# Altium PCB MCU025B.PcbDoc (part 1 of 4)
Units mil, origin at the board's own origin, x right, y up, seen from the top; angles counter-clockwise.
Board outline 2300 x 6150 mil, 6 copper layers (Top Signal, GND, Middle Signal, PWR, GND2, Bottom Signal), stack 61.64 mil thick; 237 components, 197 nets, 910 pads, 404 vias.
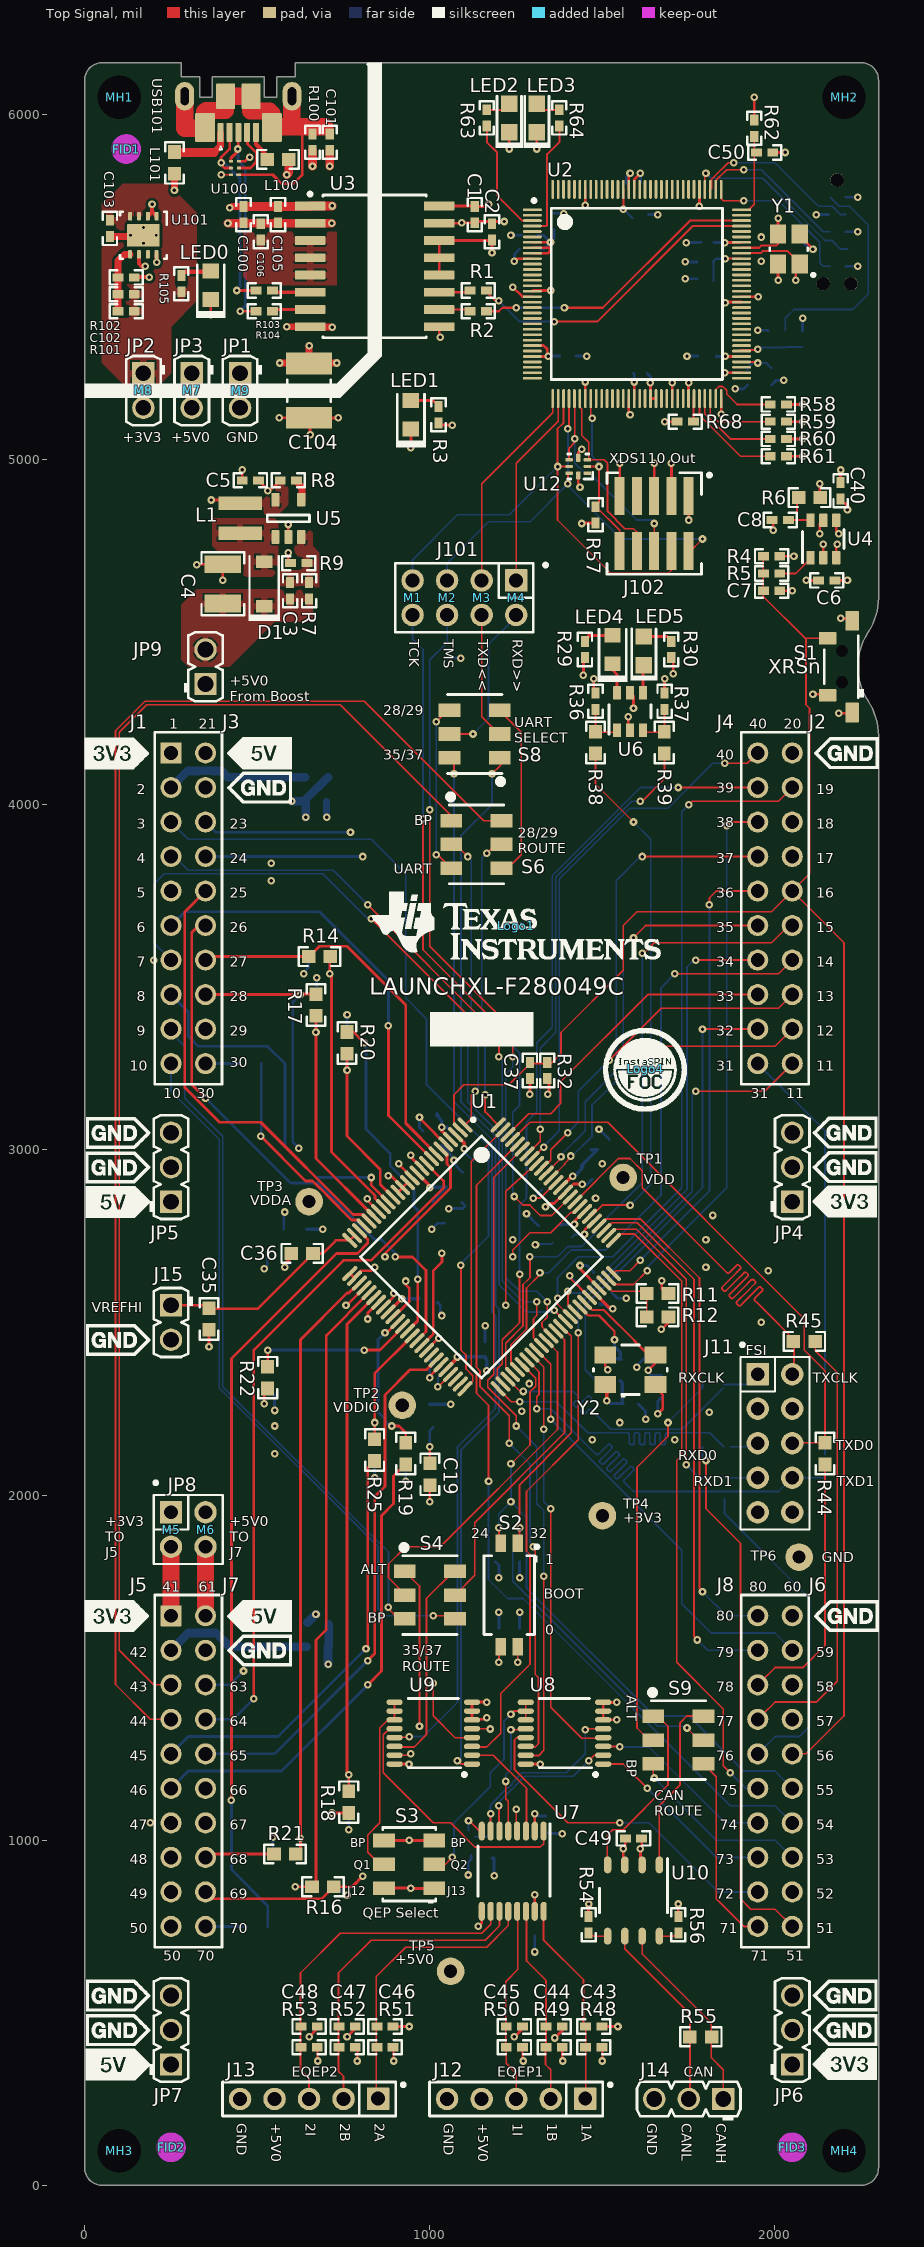
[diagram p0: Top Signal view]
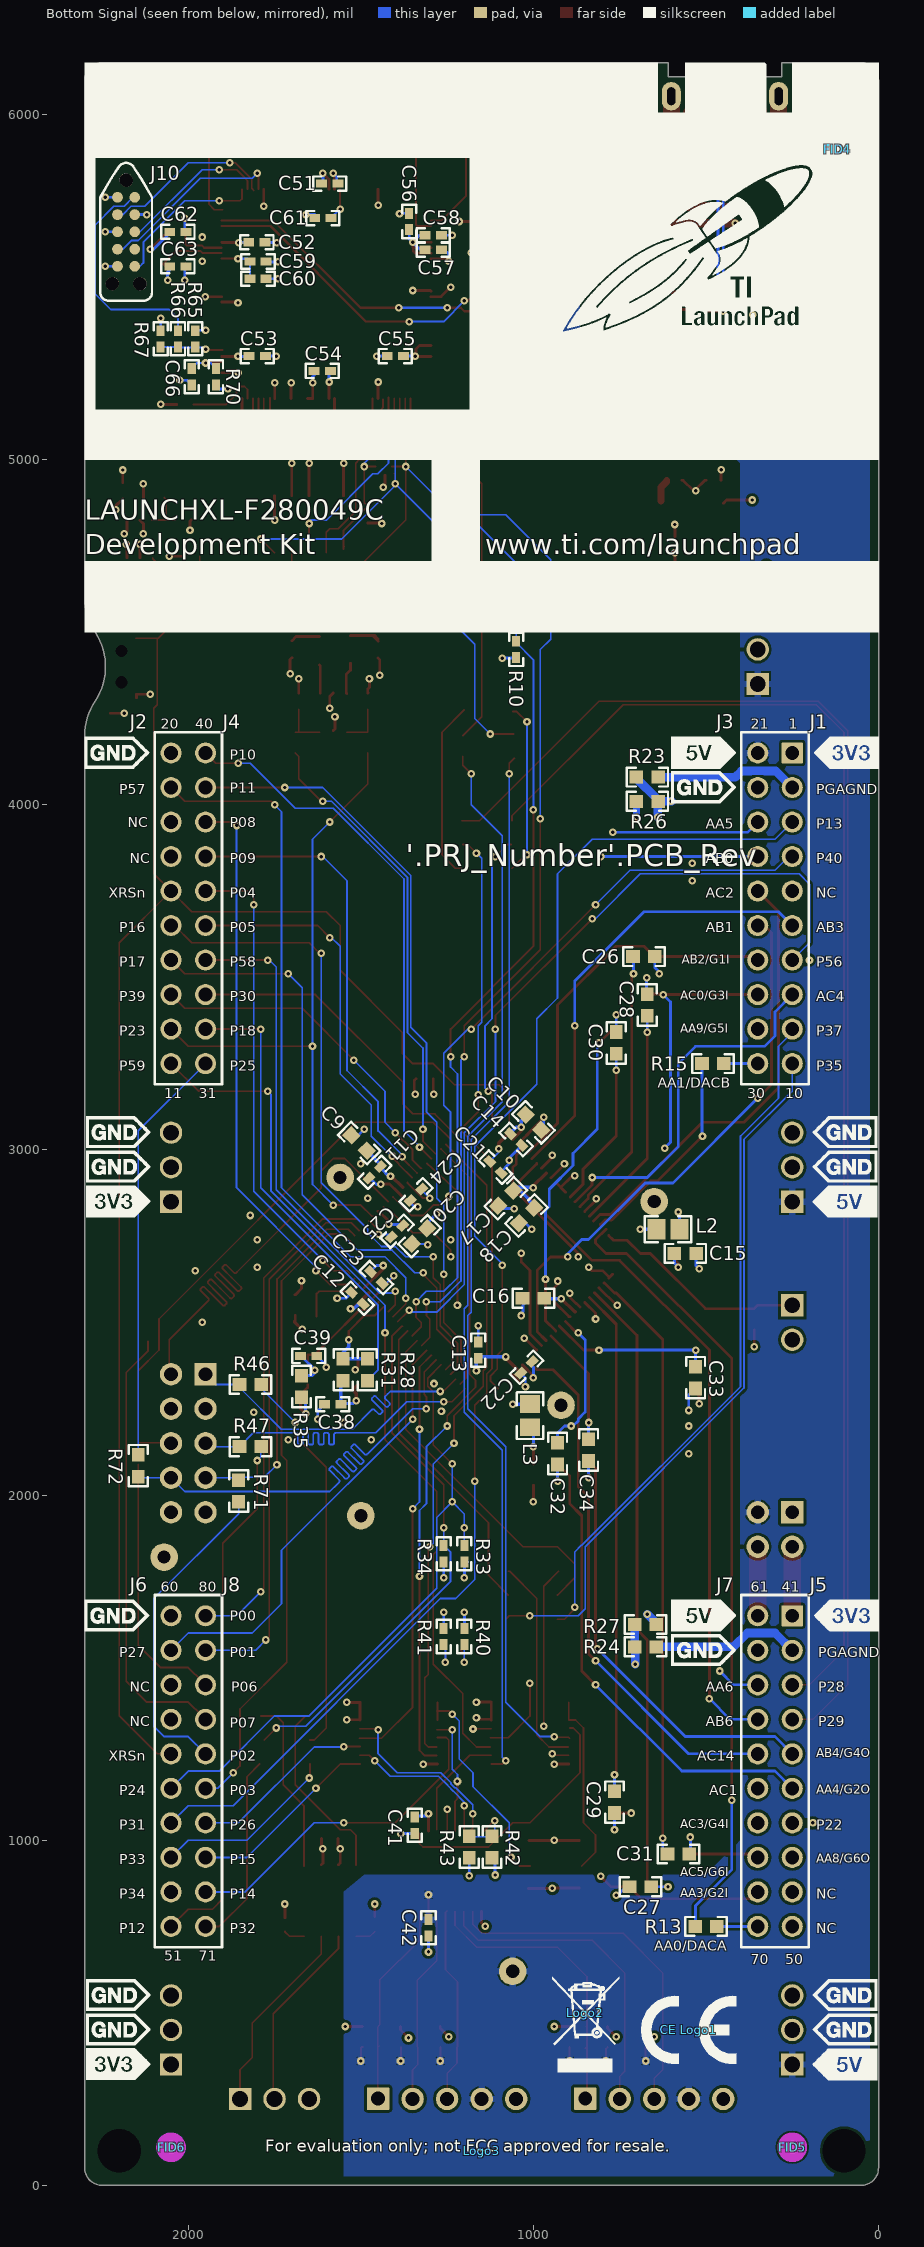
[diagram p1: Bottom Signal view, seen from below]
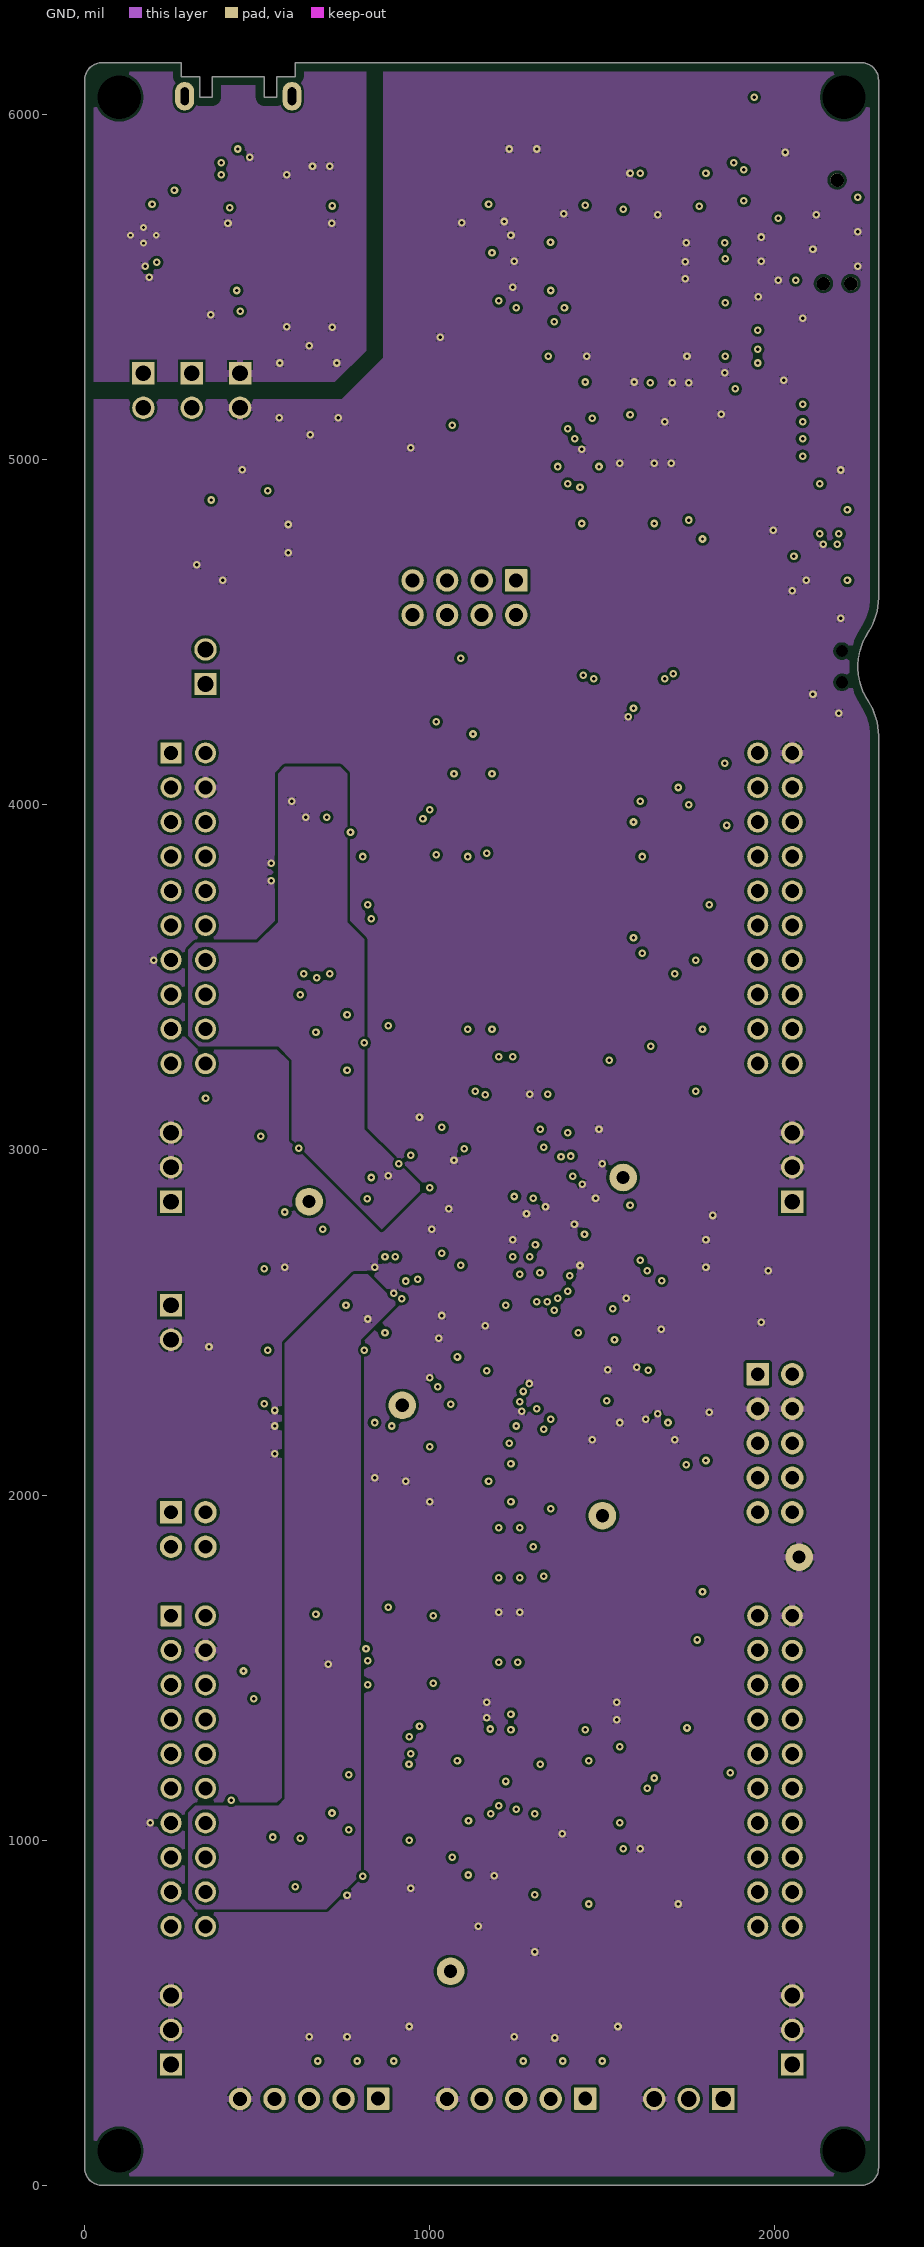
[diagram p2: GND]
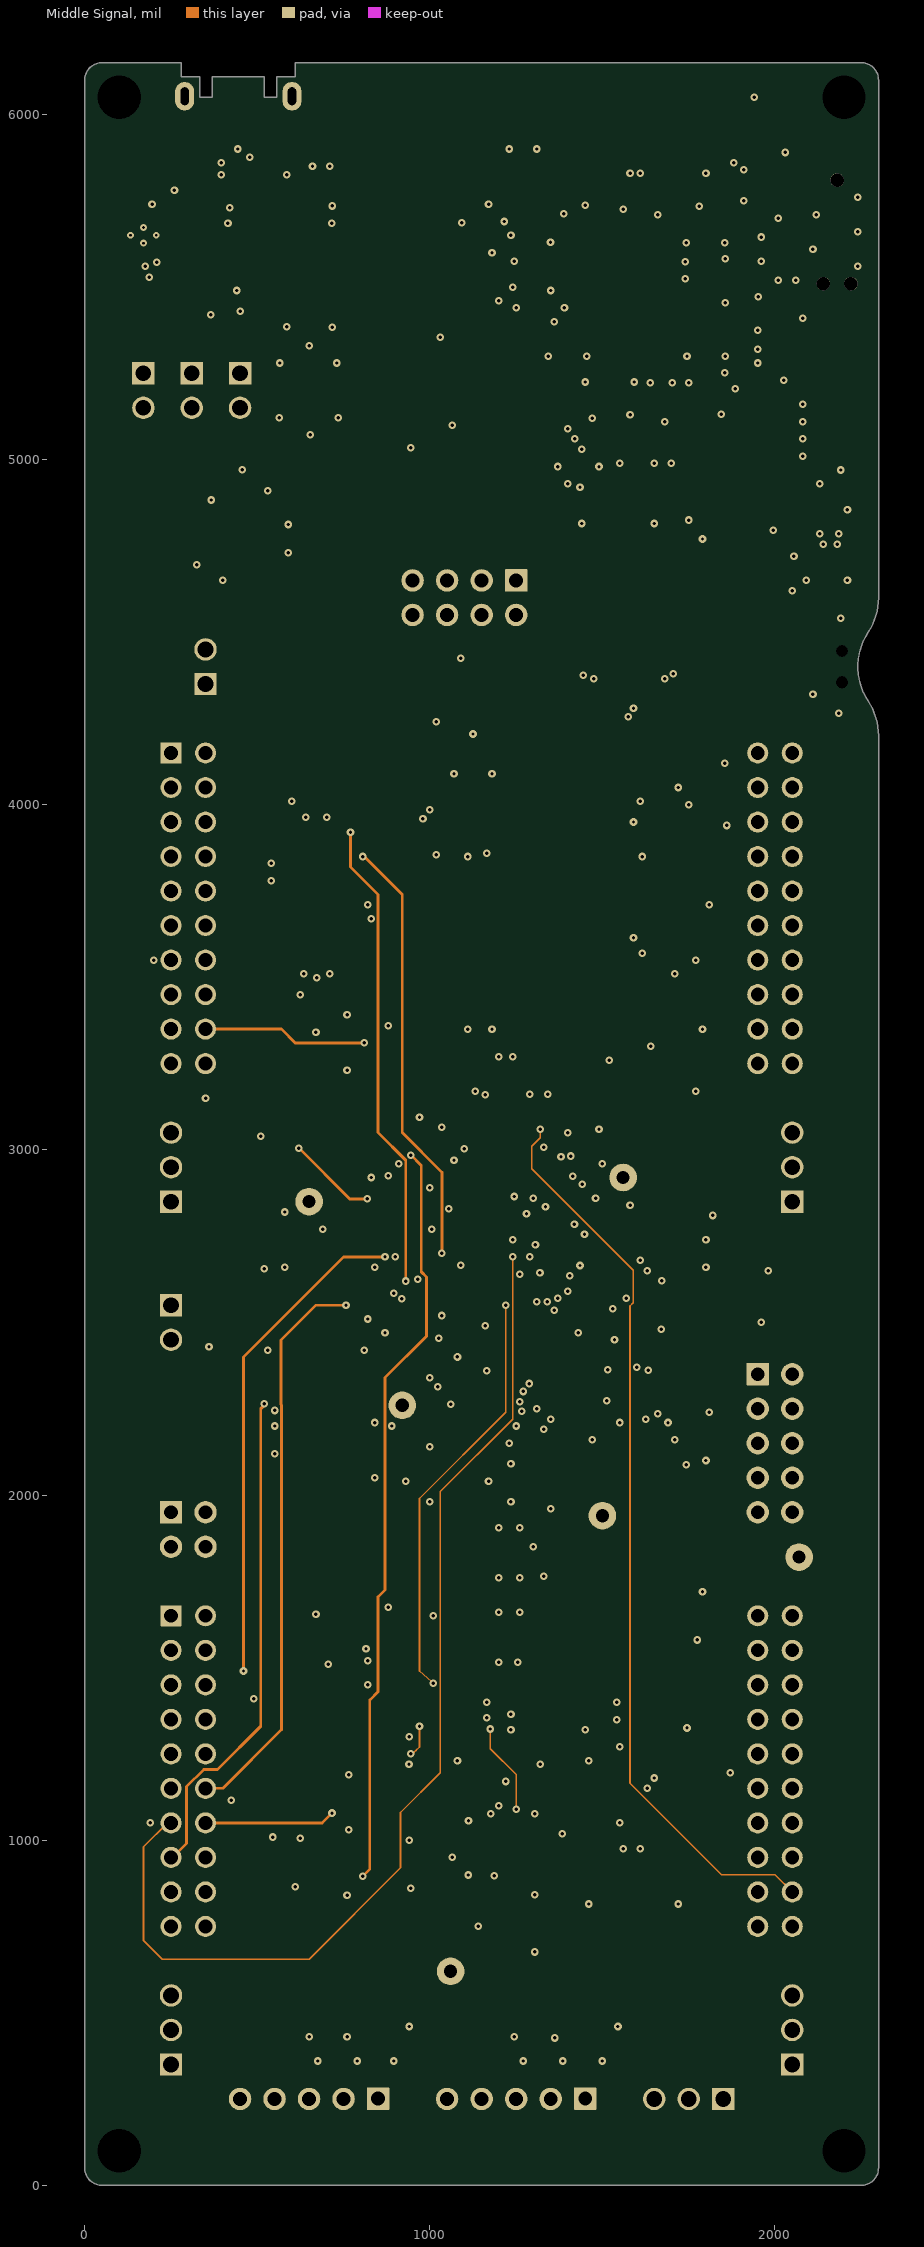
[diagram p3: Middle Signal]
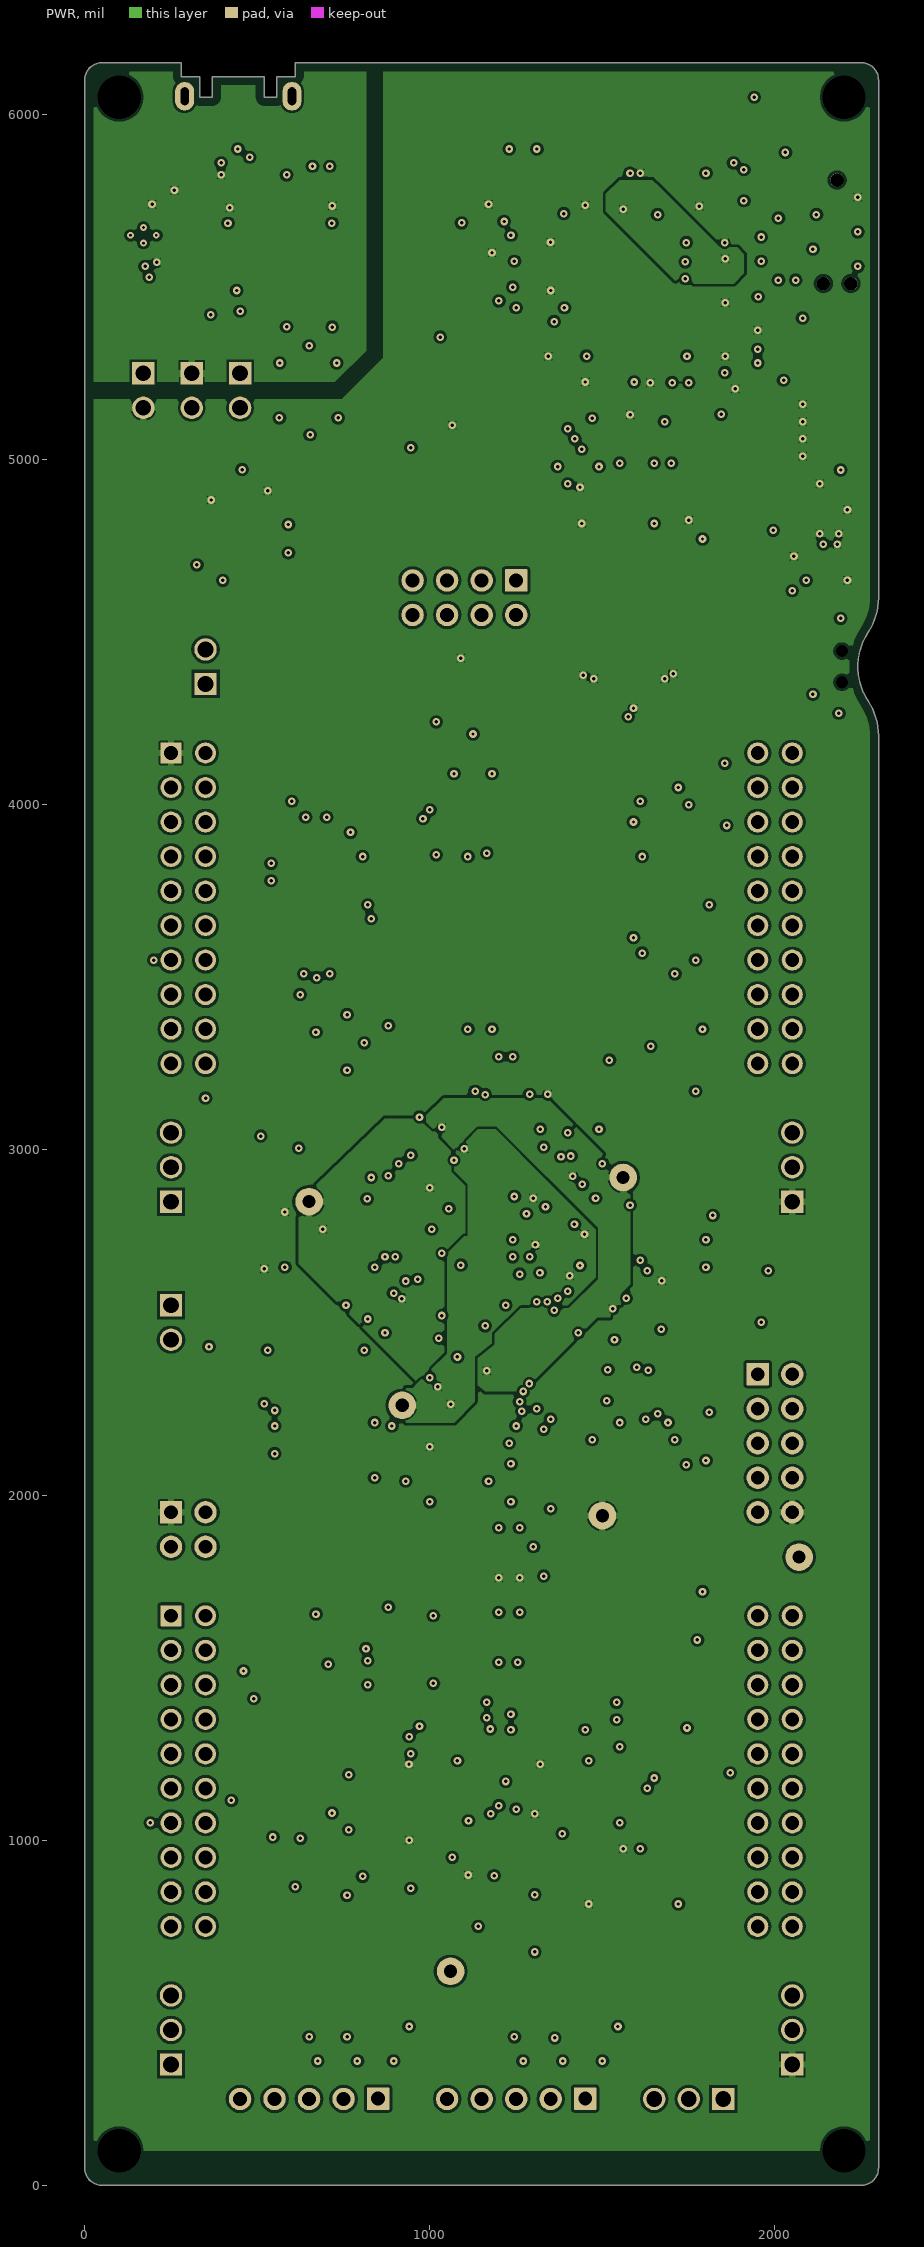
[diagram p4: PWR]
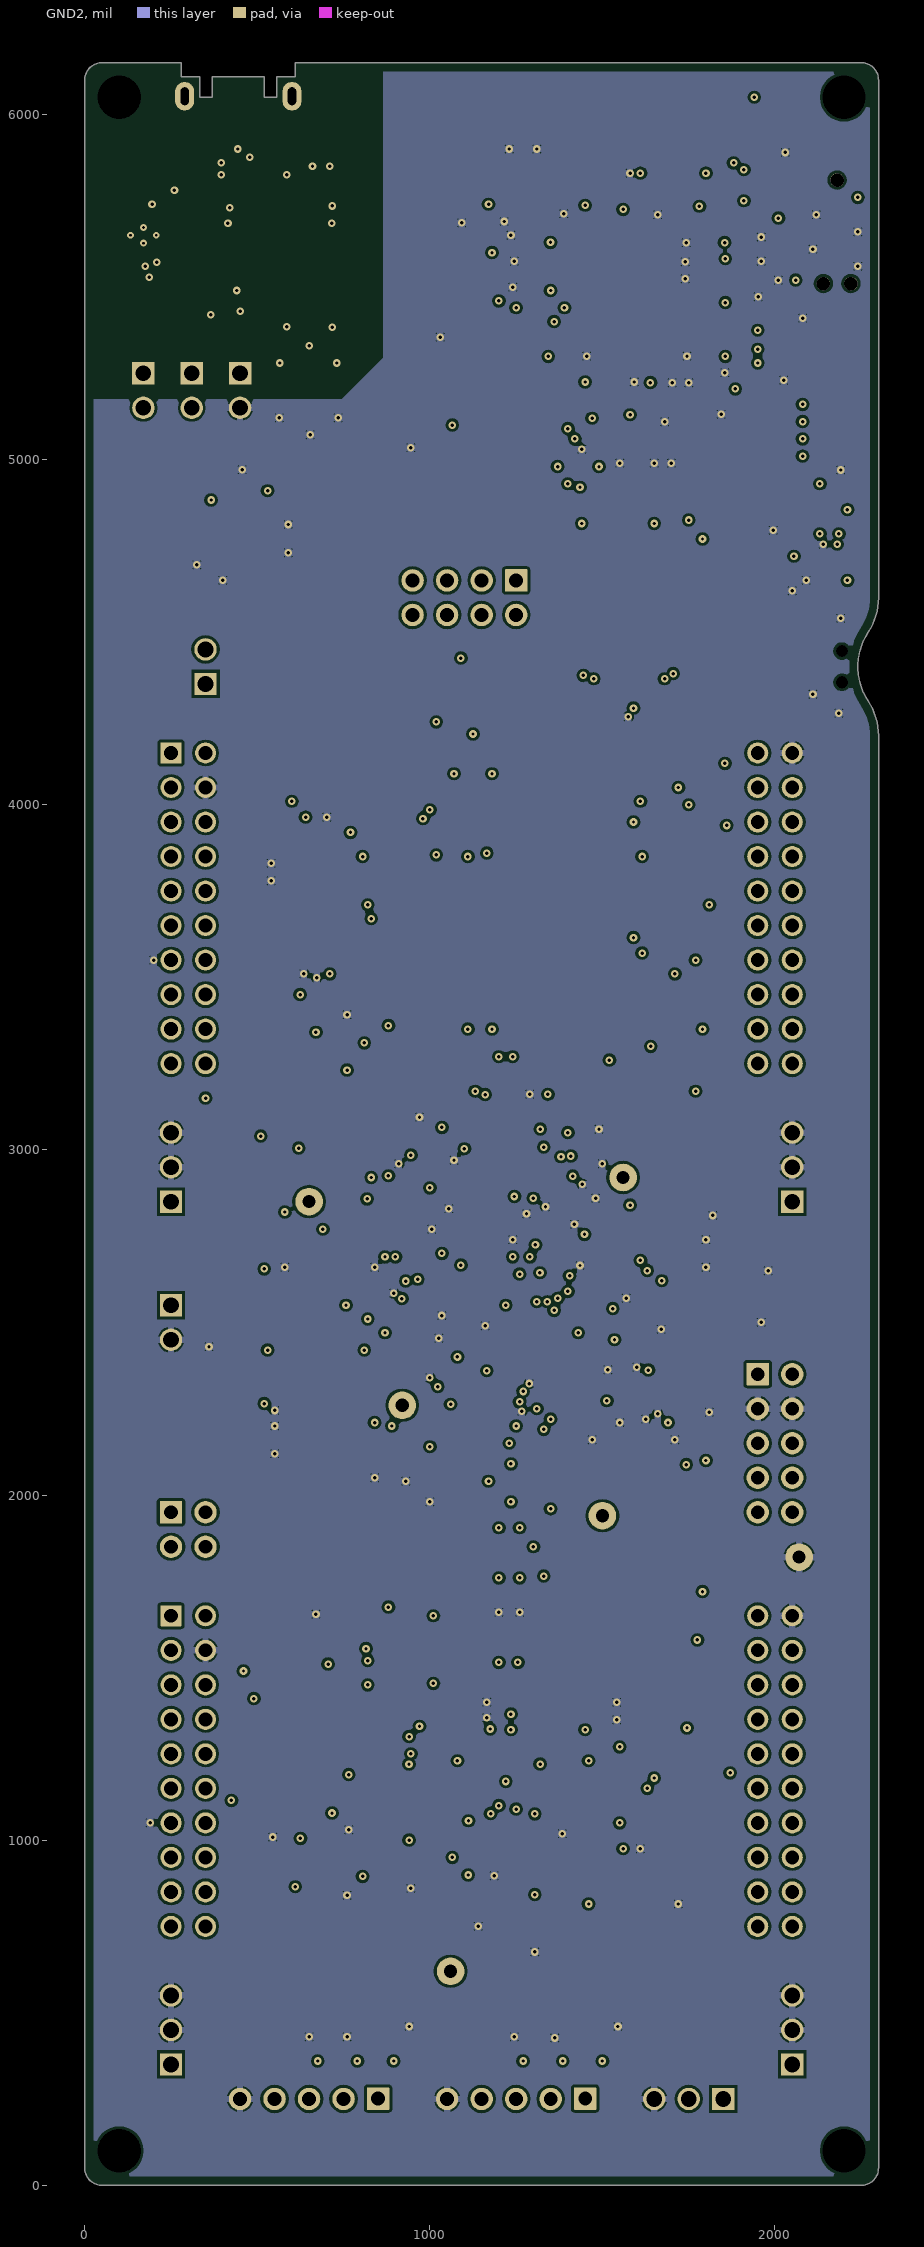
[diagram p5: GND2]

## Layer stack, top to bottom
Top Solder: solder mask 0.4, Solder Resist, Dk 3.5
Top Signal: signal copper 1.4
Dielectric 1: prepreg 6.25, FR-4, Dk 4.2
GND: signal copper 1.4
Dielectric 2: core 16.1, FR-4, Dk 4.2
Middle Signal: signal copper 1.4
Dielectric 3: prepreg 8.54, FR-4, Dk 4.2
PWR: signal copper 1.4
Dielectric 4: core 16.1, FR-4, Dk 4.2
GND2: signal copper 1.4
Dielectric 5: prepreg 6.25, FR-4, Dk 4.2
Bottom Signal: signal copper 1.4
Bottom Solder: solder mask 0.4, Solder Resist, Dk 3.5

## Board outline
50,0 cw(c50,50) 0,50 0,6100 cw(c50,6100) 50,6150 280,6150 280,6110 333,6110 333,6050 370,6050 370,6110 520,6110 520,6050 557,6050 557,6110 610,6110 610,6150 2250,6150 cw(c2250,6100) 2300,6100 2300,4600 cw(c2118.33,4600) 2270,4500 ccw(c2421.67,4400) 2270,4300 cw(c2118.33,4200) 2300,4200 2300,50 cw(c2250,50) 2250,0

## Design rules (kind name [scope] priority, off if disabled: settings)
AcuteAngle [All] p1: minimum=4.50000000000000E+0001 checktracksonly=TRUE
AssemblyTestPointUsage [All] p1: valid=2
BoardOutlineClearance BoardOutlineClearance_MountingHoles [OnCopper and InComponentClass('Mounting Holes')] p1: gap=40 ignorepadtopadclearanceinfootprint=FALSE
BoardOutlineClearance BoardOutlineClearance_Poly [OnCopper and IsPoly] p2: gap=25 ignorepadtopadclearanceinfootprint=FALSE
BoardOutlineClearance [OnCopper and Not InComponentClass('Logo') and not InComponentClass('FiducialMark') and not InRegion(1000,500,4000,800) and not InPoly] p3: gap=10 ignorepadtopadclearanceinfootprint=FALSE
Clearance Clearance_Boardedge [OnCopper and Not InComponentClass('Logo') and not InComponentClass('FiducialMark') and not IsKeepOut vs IsKeepOut] p1: gap=5 ignorepadtopadclearanceinfootprint=FALSE
Clearance Clearance_FiducialMark [InComponentClass('FiducialMark') vs InComponentClass('FiducialMark')] p2: gap=0 ignorepadtopadclearanceinfootprint=TRUE
Clearance Clearance_Keepouts [((IsTrack Or IsArc) And Not InPoly) And IsFree and IsKeepOut vs ((IsTrack Or IsArc) And Not InPoly) And IsFree and IsKeepOut] p3: gap=5 ignorepadtopadclearanceinfootprint=FALSE
Clearance Clearance_Poly [InPolygon] p4: gap=8 ignorepadtopadclearanceinfootprint=FALSE
Clearance [All] p5: gap=5 ignorepadtopadclearanceinfootprint=FALSE
ComponentClearance "ComponentClearance_overlay to overlay" [OnBottomSilkscreen vs OnTopSilkscreen] p1: gap=0 collisioncheckmode=3 verticalgap=0 showdistances=FALSE
ComponentClearance ComponentClearance_MountingHoles_FiducialMarks [InComponentClass('Mounting Holes') vs InComponentClass('FiducialMark')] p2: gap=50 collisioncheckmode=3 verticalgap=10 showdistances=FALSE
ComponentClearance ComponentClearance_Shunt [InComponentClass('Header') vs InComponentClass('Shunt')] p3: gap=0 collisioncheckmode=3 verticalgap=0 showdistances=FALSE
ComponentClearance ComponentClearance_Logo [InComponentClass('Logo')] p4: gap=0 collisioncheckmode=3 verticalgap=0 showdistances=FALSE
ComponentClearance ComponentClearance_Logo_1 [InComponentClass('Logo') vs InComponentClass('Logo')] p5: gap=0 collisioncheckmode=3 verticalgap=0 showdistances=FALSE
ComponentClearance ComponentClearance_ScrewToNut [(HasFootprint('NY PMS 440 0025 PH')) vs (HasFootprint('Keystone_1902C'))] p6: gap=5 collisioncheckmode=3 verticalgap=10 showdistances=FALSE
ComponentClearance ComponentClearance_MountingHoles [InComponentClass('Mounting Holes')] p7: gap=250 collisioncheckmode=3 verticalgap=100000 showdistances=FALSE
ComponentClearance ComponentClearance_SmallPassives [HasFootprint('0201*') or HasFootprint('0402*') or HasFootprint('0508') or HasFootprint('0603*') or HasFootprint('0612') or HasFootprint('0805*') or HasFootprint('0815*') or HasFootprint('0830*') or HasFootprint('1206*') or HasFootprint('1210*') or HasFootprint('1808*') or HasFootprint('1812*') or HasFootprint('1825*') or HasFootprint('2010*') or HasFootprint('2220*') or HasFootprint('2225*') or HasFootprint('2512*') or HasFootprint('2728*') or HasFootprint('3518*') vs HasFootprint('0201*') or HasFootprint('0402*') or HasFootprint('0508') or HasFootprint('0603*') or HasFootprint('0612') or HasFootprint('0805*') or HasFootprint('0815*') or HasFootprint('0830*') or HasFootprint('1206*') or HasFootprint('1210*') or HasFootprint('1808*') or HasFootprint('1812*') or HasFootprint('1825*') or HasFootprint('2010*') or HasFootprint('2220*') or HasFootprint('2225*') or HasFootprint('2512*') or HasFootprint('2728*') or HasFootprint('3518*')] p8: gap=10 collisioncheckmode=3 verticalgap=0 showdistances=FALSE
ComponentClearance ComponentClearance_THtoSMT [IsThruComponent vs IsSMTComponent] p9: gap=10 collisioncheckmode=3 verticalgap=10 showdistances=FALSE
ComponentClearance ComponentClearance_THtoTH [IsThruComponent vs IsThruComponent] p10: gap=20 collisioncheckmode=3 verticalgap=30 showdistances=FALSE
DiffPairsRouting [All] p1: maxlimit=100 minlimit=10 mostfreqgap=10 toplayer_minwidth=15 toplayer_maxwidth=15 toplayer_prefwidth=15 midlayer1_minwidth=15 midlayer1_maxwidth=15 midlayer1_prefwidth=15 midlayer2_minwidth=15 midlayer2_maxwidth=15 midlayer2_prefwidth=15 midlayer3_minwidth=15 midlayer3_maxwidth=15 midlayer3_prefwidth=15 midlayer4_minwidth=15 midlayer4_maxwidth=15 midlayer4_prefwidth=15 bottomlayer_minwidth=15 bottomlayer_maxwidth=15 bottomlayer_prefwidth=15 maxuncoupledlength=1000
FabricationTestPointUsage TestPointUsage [All] p1: valid=2 allowmultiple=FALSE
FabricationTestpoint Testpoint [All] p1: side=3 testpointundercomponent=TRUE minsize=40 maxsize=100 preferedsize=60 minholesize=0 maxholesize=40 preferedholesize=32 testpointgrid=1 allowsidetop=TRUE allowsidebottom=TRUE usegrid=TRUE gridtolerance=0.01
FanoutControl Fanout_LCC [IsLCC] p1: bgadir=Out bgaviamode=Centered fanoutstyle=Auto fanoutdirection=Alternating viagrid=1 // Fanout_LCC (Default Rule)
FanoutControl Fanout_BGA [IsBGA] p2: bgadir=Out bgaviamode=Centered fanoutstyle=Auto fanoutdirection=Alternating viagrid=1 // Fanout_BGA (Default Rule)
FanoutControl Fanout_Default [All] p4: bgadir=Out bgaviamode=Centered fanoutstyle=Auto fanoutdirection=Alternating viagrid=1 // Fanout_Default (Default Rule)
FanoutControl Fanout_Small [(CompPinCount < 5)] p5: bgadir=Out bgaviamode=Centered fanoutstyle=Auto fanoutdirection=OutThenIn viagrid=1 // Fanout_Small (Default Rule)
HoleSize [All] p1: absolutevalues=TRUE maxlimit=251 minlimit=10 maxpercent=80.000 minpercent=20.000
MatchedLengths FSIRX [InNetClass('FSIRX')] p1: tolerance=25 checknetsindiffpair=FALSE checkdiffpairvsdiffpair=TRUE checkxsignals=TRUE checkothers=TRUE
MatchedLengths FSITX [InNetClass('FSITX')] p2: tolerance=25 checknetsindiffpair=FALSE checkdiffpairvsdiffpair=TRUE checkxsignals=TRUE checkothers=TRUE
MinimumAnnularRing MinimumAnnularRing_ThermalPadVias [IsVia and InAnyComponent] p1: minimumring=5
MinimumAnnularRing [All] p2: minimumring=6
MinimumSolderMaskSliver MinimumSolderMaskSliver_Logo [InComponentClass('Logo') vs InComponentClass('Logo')] p1: minsoldermaskwidth=0.7
MinimumSolderMaskSliver [All] p2: minsoldermaskwidth=3
PlaneClearance [All] p1: clearance=5
PlaneConnect [All] p1: planeconnectstyle=Relief reliefexpansion=10 reliefentries=4 reliefconductorwidth=25 reliefairgap=10
PolygonConnect [All] p1: connectstyle=Relief reliefconductorwidth=20 reliefentries=4 polygonreliefangle="90 Angle" airgapwidth=5
RoutingVias ThermalPadVias [IsVia and InAnyComponent] p1: holewidth=7.87 width=19.68 viastyle="Through Hole" minholewidth=7.87 minwidth=19.68 maxholewidth=12.99 maxwidth=23.62
RoutingVias [All] p2: holewidth=10 width=22 viastyle="Through Hole" minholewidth=10 minwidth=22 maxholewidth=40 maxwidth=65
SilkToBoardRegionClearance [Not ((IsComment or IsDesignator) And (Hide <> 'False')) and not InRegion(1000,500,4000,800)] p1:
SilkToSilkClearance SilkToSilkClearance_Pb-FreeLogo [(HasFootprint('Pb-Free_Overlay_Medium') OR HasFootprint('Pb-Free_Overlay_Small')) vs (HasFootprint('Pb-Free_Overlay_Medium') OR HasFootprint('Pb-Free_Overlay_Small'))] p1: silktosilkclearance=0
SilkToSilkClearance [All] p2: silktosilkclearance=3
SilkToSolderMaskClearance SilkToComponentPadClearance [(IsPad or IsFill or IsRegion) and InAnycomponent] p1: minsilkscreentomaskgap=3 clearancetoexposedcopper=TRUE
SilkToSolderMaskClearance "Silk to Solder Mask Opening" [All] p2: minsilkscreentomaskgap=3 clearancetoexposedcopper=TRUE
SolderMaskExpansion [All] p1: expansion=2
Width Analog [InNetClass('Analog')] p1: maxlimit=25 minlimit=8 preferedwidth=8
Width [All] p2: maxlimit=100 minlimit=5 preferedwidth=5 checkconnectedcopper=TRUE
14 further rules are at their usual default settings.

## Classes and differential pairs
net class Analog: ADCINA0 ADCINA1 ADCINA2 ADCINA3_P2I ADCINA4_P2OF ADCINA5 ADCINA6 ADCINA8_P6OF ADCINA9_P5I ADCINB0 ADCINB1 ADCINB2_P1I ADCINB3 ADCINB4_P4OF ADCINC0_P3I ADCINC1 ADCINC2 ADCINC3_P4I ADCINC4 ADCINC5_P6I ADCINC14 GND NetC26_2 NetC27_2 NetC28_2 NetC29_2 NetC30_2 NetC31_2 NetC32_1 NetC33_1 NetC34_1 NetC35_1 NetR13_2 NetR15_2 NetR23_1 NetR24_1 PGA135_GND PGA246_GND
component class MCU025B_XDS110_USB_Power: C1 C2 C3 C4 C5 C6 C7 C8 C100 C101 C102 C103 C104 C105 C106 D1 JP1 JP2 JP3 JP4 JP5 JP6 JP7 JP9 JP10 L1 L100 L101 LED0 LED1 R1 R2 R3 R4 R5 R6 R7 R8 R9 R100 R101 R102 R103 R104 R105 TP1 TP2 TP3 TP4 TP5 TP6 U3 U4 U5 U100 U101 USB101
component class MCU025B_XDS110_Target_Interface: J101 J102 R57 U12
component class MCU025B_XDS110_MCU: C50 C51 C52 C53 C54 C55 C56 C57 C58 C59 C60 C61 C62 C63 C66 J10 LED2 LED3 R58 R59 R60 R61 R62 R63 R64 R65 R66 R67 R68 R70 R? U2 Y1
component class MCU025B_F280049C_Device: C9 C10 C11 C12 C13 C14 C15 C16 C17 C18 C19 C20 C21 C22 C23 C24 C25 C26 C27 C28 C29 C30 C31 C32 C33 C34 C35 C36 C67 J15 L2 L3 R10 R11 R12 R13 R14 R15 R16 R17 R18 R19 R20 R21 R22 R23 R24 R25 R26 R27 U1
component class MCU025B_Connectors: C43 C44 C45 C46 C47 C48 C49 J1 J2 J5 J6 J11 J12 J13 J14 JP8 R48 R49 R50 R51 R52 R53 R54 R55 R56 U10
component class MCU025B_AltRouting_Misc: C37 C38 C39 C40 C41 C42 LED4 LED5 R28 R29 R30 R31 R32 R33 R34 R35 R36 R37 R38 R39 R40 R41 R42 R43 R44 R45 R46 R47 R71 R72 S1 S2 S3 S4 S6 S8 S9 U6 U7 U8 U9 Y2
component class Header: J11 J12 J13 J14 J15 J101 JP1 JP2 JP3 JP4 JP5 JP6 JP7 JP8 JP9 JP10
component class AssemblyNote: ZZ2 ZZ3 ZZ4
component class FiducialMark: FID1 FID2 FID3 FID4 FID5 FID6
component class MCU025B_Hardware: "CE Logo1" FID1 FID2 FID3 FID4 FID5 FID6 Logo1 Logo2 Logo3 Logo4 M1 M2 M3 M4 M5 M6 M7 M8 M9 MH1 MH2 MH3 MH4 ZZ2 ZZ3 ZZ4
component class Logo: Logo1 Logo4
net class FSIRX: GPIO2_FSIRXD1 GPIO12_FSIRXD0 GPIO33_FSIRXCLK
net class FSITX: GPIO6_FSITXD0 GPIO7_FSITXCLK GPIO25_FSITXD1
component class Shunt: M1 M2 M3 M4 M5 M6 M7 M8 M9

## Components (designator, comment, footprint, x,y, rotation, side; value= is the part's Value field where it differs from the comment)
C1 "GRM155R71A104KA01D" 0402 1130,5710 r90 top value=0.1uF
C2 "GRM155R71A104KA01D" 0402 1180,5660 r270 top value=0.1uF
C3 "GRM1555C1H821JA01D" 0402 595,4620 r90 top value=820pF
C4 "GRM32DR71E106KA12L" 1210_220 400,4640 r90 top value=10uF
C5 "GRM155R60J475ME47D" 0402 480,4940 r180 top value=4.7uF
C6 "GRM155R71A104KA01D" 0402 2150,4650 r0 top value=0.1uF
C7 "GRM155R71E103KA01D" 0402 1990,4620 r0 top value=0.01uF
C8 "GRM155R71E103KA01D" 0402 2015,4825 r180 top value=0.01uF
C9 "GRM188R61A106ME69D" 0603 1505,3020 r225 bottom value=10uF
C10 "GRM188R61A106ME69D" 0603 1000,3080 r45 bottom value=10uF
C11 "GRM155R71A104KA01D" 0402 1460,2935 r315 bottom value=0.1uF
C12 "GRM155R71A104KA01D" 0402 1510,2570 r45 bottom value=0.1uF
C13 "GRM155R71A104KA01D" 0402 1160,2420 r90 bottom value=0.1uF
C14 "GRM155R71A104KA01D" 0402 1050,3030 r225 bottom value=0.1uF
C15 "GRM188R61A225KE34D" 0603 560,2700 r0 bottom value=2.2uF
C16 "GRM188R61A225KE34D" 0603 1000,2570 r0 bottom value=2.2uF
C17 "GRM188R61A225KE34D" 0603 1080,2860 r315 bottom value=2.2uF
C18 "GRM188R61A225KE34D" 0603 1020,2810 r315 bottom value=2.2uF
C19 "GRM188R61A106ME69D" 0603 1000,2060 r270 top value=10uF
C20 "GRM188R61A106ME69D" 0603 1330,2750 r135 bottom value=10uF
C21 "GRM155R71A104KA01D" 0402 1110,2950 r45 bottom value=0.1uF
C22 "GRM155R71A104KA01D" 0402 1020,2370 r315 bottom value=0.1uF
C23 "GRM155R71A104KA01D" 0402 1455,2630 r225 bottom value=0.1uF
C24 "GRM155R71A104KA01D" 0402 1340,2870 r135 bottom value=0.1uF
C25 "GRM155R71A104KA01D" 0402 1395,2764 r315 bottom value=0.1uF
C26 "GRM1885C1H331JA01D" 0603 680,3560 r0 bottom value=330pF
C27 "GRM1885C1H331JA01D" 0603 690,865 r180 bottom value=330pF
C28 "GRM1885C1H331JA01D" 0603 670,3420 r270 bottom value=330pF
C29 "GRM1885C1H331JA01D" 0603 765,1110 r90 bottom value=330pF
C30 "GRM1885C1H331JA01D" 0603 760,3310 r270 bottom value=330pF
C31 "GRM1885C1H331JA01D" 0603 580,960 r0 bottom value=330pF
C32 "GRM1885C1H331JA01D" 0603 930,2120 r270 bottom value=330pF
C33 "GRM1885C1H331JA01D" 0603 530,2340 r270 bottom value=330pF
C34 "GRM1885C1H331JA01D" 0603 840,2130 r270 bottom value=330pF
C35 "GRM188R61A225KE34D" 0603 360,2510 r270 top value=2.2uF
C36 "GRM188R61A225KE34D" 0603 630,2700 r180 top value=2.2uF
C37 "GRM155R71A104KA01D" 0402 1290,3230 r90 top value=0.1uF
C38 "GRM1555C1H150JA01D" 0402 1581.21,2262.93 r0 bottom value=15pF
C39 "GRM1555C1H150JA01D" 0402 1651.21,2402.93 r180 bottom value=15pF
C40 "GRM155R71A104KA01D" 0402 2190,4910 r270 top value=0.1uF
C41 "GRM155R71A104KA01D" 0402 1344,1043 r270 bottom value=0.1uF
C42 "GRM155R71A104KA01D" 0402 1304,746 r90 bottom value=0.1uF
C43 "GRM155R71H102KA01D" 0402 1475,460 r0 top value=1000pF
C44 "GRM155R71H102KA01D" 0402 1360,460 r0 top value=1000pF
C45 "GRM155R71H102KA01D" 0402 1245,460 r0 top value=1000pF
C46 "GRM155R71H102KA01D" 0402 870,460 r0 top value=1000pF
C47 "GRM155R71H102KA01D" 0402 760,460 r0 top value=1000pF
C48 "GRM155R71H102KA01D" 0402 650,460 r0 top value=1000pF
C49 "GRM155R71A104KA01D" 0402 1590,1005 r180 top value=0.1uF
C50 "GRM155R71E103KA01D" 0402 1970,5890 r0 top value=0.01uF
C51 "GRM155R71E103KA01D" 0402 1590,5800 r180 bottom value=0.01uF
C52 "GRM155R71E103KA01D" 0402 1801,5630 r180 bottom value=0.01uF
C53 "GRM155R71E103KA01D" 0402 1800,5300 r180 bottom value=0.01uF
C54 "GRM155R70J104KA01D" 0402 1612,5257 r180 bottom value=0.1uF
C55 "GRM155R70J104KA01D" 0402 1400,5300 r0 bottom value=0.1uF
C56 "GRM155R61A105KE15D" 0402 1360,5690 r90 bottom value=1uF
C57 "GRM155R61A105KE15D" 0402 1290,5608 r180 bottom value=1uF
C58 "GRM155R71E103KA01D" 0402 1290,5650 r180 bottom value=0.01uF
C59 "GRM155R60J225KE95D" 0402 1798,5574 r180 bottom value=2.2uF
C60 "GRM155R70J104KA01D" 0402 1798,5524 r180 bottom value=0.1uF
C61 "GRM155R61A105KE15D" 0402 1610,5700 r0 bottom value=1uF
C62 "GRM1555C1H120JA01D" 0402 2030,5660 r0 bottom value=12pF
C63 "GRM1555C1H120JA01D" 0402 2030,5560 r180 bottom value=12pF
C66 "GRM155R70J104KA01D" 0402 1990,5240 r270 bottom value=0.1uF
C100 "GRM155R60J225KE95D" 0402 460,5710 r270 top value=2.2uF
C101 "GRM155R71H332KA01D" 0402 710,5920 r270 top value=3300pF
C102 "GRM1555C1H150JA01D" 0402 120,5479 r180 top value=15pF
C103 "GRM155R60J225KE95D" 0402 73,5670 r270 top value=2.2uF
C104 "1812SC103KAT1A" 1812 650,5200 r90 top value=0.01uF
C105 "GRM155R71A104KA01D" 0402 560,5710 r90 top value=0.1uF
C106 "GRM155R71A104KA01D" 0402 510,5660 r270 top value=0.1uF
"CE Logo1" "CE Mark" CE_Mark_5mm 550,450 r180 bottom
D1 "1N5819HW-7-F" SOD-123 520,4640 r90 top value=40V
FID1 "Fiducial" Fiducial10-20 120,5900 r0 top
FID2 "Fiducial" Fiducial10-20 250,110 r0 top
FID3 "Fiducial" Fiducial10-20 2050,110 r0 top
FID4 "Fiducial" Fiducial10-20 120,5900 r180 bottom
FID5 "Fiducial" Fiducial10-20 250,110 r180 bottom
FID6 "Fiducial" Fiducial10-20 2050,110 r180 bottom
J1 "SSQ-110-03-T-D" BoosterPack_40pin_J1J3 300,3700 r180 bottom locked
J2 "SSQ-110-03-T-D" BoosterPack_40pin_J2J4 2000,3700 r180 bottom locked (schematic designator J4)
J5 "SSQ-110-03-T-D" BoosterPack_40pin_J1J3 300,1200 r180 bottom locked
J6 "SSQ-110-03-T-D" BoosterPack_40pin_J2J4 2000,1200 r180 bottom locked (schematic designator J8)
J10 "TC2050-IDC-NL-FP" Tag_TC2050-NL 2180,5660 r180 bottom locked
J11 "TSW-105-07-G-D" TSW-105-07-G-D 2000,2150 r270 top
J12 "TSW-105-07-G-S" TSW-105-07-X-S 1250,250 r180 top locked
J13 "TSW-105-07-G-S" TSW-105-07-X-S 650,250 r180 top locked
J14 "61300311121" WURTH_61300311121 1750,250 r180 top locked
J15 "61300211121" WURTH_61300211121 250,2500 r270 top locked
J101 "TSW-104-07-G-D" TSW-104-07-G-D 1100,4600 r180 top
J102 "FTSH-105-01-F-DV-K" Samtec_FTSH-105-01-x-DV-K 1650,4815 r270 top
JP1 "61300211121" WURTH_61300211121 450,5200 r270 top
JP2 "61300211121" WURTH_61300211121 170,5200 r270 top
JP3 "61300211121" WURTH_61300211121 310,5200 r270 top
JP4 "61300311121" WURTH_61300311121 2050,2950 r90 top locked
JP5 "61300311121" WURTH_61300311121 250,2950 r90 top locked
JP6 "61300311121" WURTH_61300311121 2050,450 r90 top
JP7 "61300311121" WURTH_61300311121 250,450 r90 top locked
JP8 "TSW-102-07-G-D" TSW-102-07-G-D 300,1900 r270 top
JP9 "61300211121" WURTH_61300211121 350,4400 r90 top
L1 "744025003" WE-TPC_2828 450,4830 r270 top value=3.3uH
L2 "BKP2125HS600-T" 0805 610,2770 r0 bottom value="60 ohm"
L3 "BLM21PG221SN1D" 0805 1010,2230 r90 bottom value="220 ohm"
L100 "742792620" 0603 560,5870 r0 top value="100 ohm"
L101 "742792620" 0603 260,5860 r270 top value="100 ohm"
LED0 "150080SS75000" WL-SMCW_RED_0805 365,5505 r90 top value=Red
LED1 "150080SS75000" WL-SMCW_RED_0805 945,5130 r90 top value=Red
LED2 "LTST-C170TBKT" LTST-C170TBKT_Blue 1230,5990 r270 top value=Blue
LED3 "LTST-C170TBKT" LTST-C170TBKT_Blue 1310,5990 r270 top value=Blue
LED4 "150080SS75000" WL-SMCW_RED_0805 1529.37,4449.84 r90 top value=Red
LED5 "LTST-C171GKT" LED_LTST-C171 1620,4446 r270 top value=Green
Logo1 "Texas Instruments" TI_Stacked_Overlay_Small 1250,3650 r0 top
Logo2 "WEEE logo" WEEE_Minimum 850,500 r180 bottom
Logo3 "FCC disclaimer" FCC_disclaimer 1150,100 r180 bottom
Logo4 "INSTASPIN_FOC_LOGO" INSTASPIN_FOC_LOGO 1625,3235 r0 top
M1 "60900213421" Wurth_60900213421 950,4600 r270 top
M2 "60900213421" Wurth_60900213421 1050,4600 r90 top
M3 "60900213421" Wurth_60900213421 1150,4600 r90 top
M4 "60900213421" Wurth_60900213421 1250,4600 r90 top
M5 "60900213421" Wurth_60900213421 250,1900 r90 top
M6 "60900213421" Wurth_60900213421 350,1900 r90 top
M7 "60900213421" Wurth_60900213421 310,5201 r90 top
M8 "60900213421" Wurth_60900213421 170,5201 r90 top
M9 "60900213421" Wurth_60900213421 450,5200 r90 top
MH1 "MTG_NoPads" NPTH125mil 100,6050 r0 top
MH2 "MTG_NoPads" NPTH125mil 2200,6050 r0 top
MH3 "MTG_NoPads" NPTH125mil 100,100 r0 top
MH4 "MTG_NoPads" NPTH125mil 2200,100 r0 top
R1 "CRCW040224R3FKED" 0402 1140,5490 r0 top value=24.3
R2 "CRCW040224R3FKED" 0402 1140,5430 r0 top value=24.3
R3 "CRCW0402680RJNED" 0402 1025,5130 r270 top value=680
R4 "CRCW04022K20JNED" 0402 1990,4720 r0 top value=2.2k
R5 "CRCW04020000Z0ED" 0402 1990,4670 r180 top value=0
R6 "CRCW06032K20JNEA" 0603 2100,4890 r0 top value=2.2k
R7 "RC0402FR-0730K1L" 0402 650,4620 r270 top value=30.1k
R8 "CRCW040210K0JNED" 0402 590,4940 r180 top value=10k
R9 "CRCW040210K0JNED" 0402 620,4700 r0 top value=10k
R10 "CRCW04022K20JNED" 0402 1050,4450 r270 bottom value=2.2k
R11 "CRCW06030000Z0EA" 0603 1660,2584 r0 top value=0
R12 "CRCW06030000Z0EA" 0603 1660,2516 r0 top value=0
R13 "CRCW06030000Z0EA" 0603 500,750 r0 bottom value=0
R14 "CRCW06030000Z0EA" 0603 680,3560 r180 top value=0
R15 "CRCW06030000Z0EA" 0603 480,3250 r0 bottom value=0
R16 "CRCW06030000Z0EA" 0603 690,865 r0 top value=0
R17 "CRCW06030000Z0EA" 0603 670,3420 r90 top value=0
R18 "CRCW06030000Z0EA" 0603 765,1110 r270 top value=0
R19 "CRCW06030000Z0EA" 0603 930,2120 r90 top value=0
R20 "CRCW06030000Z0EA" 0603 760,3310 r90 top value=0
R21 "CRCW06030000Z0EA" 0603 580,960 r180 top value=0
R22 "CRCW06030000Z0EA" 0603 530,2340 r90 top value=0
R23 "CRCW06030000Z0EA" 0603 670,4080 r180 bottom value=0
R24 "CRCW06030000Z0EA" 0603 675,1560 r180 bottom value=0
R25 "CRCW06030000Z0EA" 0603 840,2130 r90 top value=0
R26 "CRCW06030000Z0EA" 0603 670,4010 r180 bottom value=0
R27 "CRCW06030000Z0EA" 0603 675,1625 r0 bottom value=0
R28 "CRCW06030000Z0EA" 0603 1481.21,2362.93 r90 bottom value=0
R29 "CRCW0402680RJNED" 0402 1449.37,4449.84 r270 top value=680
R30 "CRCW0402680RJNED" 0402 1699.37,4449.84 r270 top value=680
R31 "CRCW06030000Z0EA" 0603 1551.21,2362.93 r90 bottom value=0
R32 "CRCW04022K20JNED" 0402 1340,3230 r270 top value=2.2k
R33 "CRCW040256K0JNED" 0402 1200,1830 r270 bottom value=56k
R34 "CRCW040256K0JNED" 0402 1260,1830 r270 bottom value=56k
R35 "CRCW06030000Z0EA" 0603 1671.92,2314.64 r270 bottom value=0
R36 "CRCW040210M0JNED" 0402 1480,4300 r90 top value=10Meg
R37 "CRCW040210M0JNED" 0402 1680,4300 r90 top value=10Meg
R38 "CRCW06030000Z0EA" 0603 1480,4180 r90 top value=0
R39 "CRCW06030000Z0EA" 0603 1679,4180 r90 top value=0
R40 "CRCW04022K20JNED" 0402 1200,1590 r270 bottom value=2.2k
R41 "CRCW04022K20JNED" 0402 1260,1590 r270 bottom value=2.2k
R42 "CRCW06032K20JNEA" 0603 1120,980 r90 bottom value=2.2k
R43 "CRCW06030000Z0EA" 0603 1186,980 r90 bottom value=0
R44 "CRCW06030000Z0EA" 0603 2145,2120 r270 top value=0
R45 "CRCW06030000Z0EA" 0603 2085,2445 r0 top value=0
R46 "CRCW06030000Z0EA" 0603 1820,2320 r180 bottom value=0
R47 "CRCW06030000Z0EA" 0603 1820,2140 r180 bottom value=0
R48 "CRCW04021K00FKED" 0402 1475,400 r0 top value=1.00k
R49 "CRCW04021K00FKED" 0402 1360,400 r0 top value=1.00k
R50 "CRCW04021K00FKED" 0402 1245,400 r0 top value=1.00k
R51 "CRCW04021K00FKED" 0402 870,400 r0 top value=1.00k
R52 "CRCW04021K00FKED" 0402 760,400 r0 top value=1.00k
R53 "CRCW04021K00FKED" 0402 650,400 r0 top value=1.00k
R54 "CRCW040210K0FKED" 0402 1460,755 r90 top value=10.0k
R55 "RC0603FR-07120RL" 0603 1785,430 r0 top value=120
R56 "CRCW040210K0FKED" 0402 1720,755 r270 top value=10.0k
R57 "CRCW04023K30JNED" 0402 1480,4840 r270 top value=3.3k
R58 "CRCW04021K00JNED" 0402 2010,5160 r0 top value=1.0k
R59 "CRCW04021K00JNED" 0402 2010,5110 r0 top value=1.0k
R60 "CRCW04021K00JNED" 0402 2010,5060 r0 top value=1.0k
R61 "CRCW04021K00JNED" 0402 2010,5010 r0 top value=1.0k
R62 "CRCW0402100RJNED" 0402 1940,5960 r270 top value=100
R63 "ERJ-2RKF4700X" 0402 1165,5990 r270 top value=470
R64 "ERJ-2RKF4700X" 0402 1375,5990 r270 top value=470
R65 "CRCW040210K0JNED" 0402 1980,5350 r90 bottom value=10k
R66 "CRCW0402100RJNED" 0402 2030,5350 r270 bottom value=100
R67 "CRCW040210K0JNED" 0402 2080,5350 r270 bottom value=10k
R68 "CRCW04024K87FKED" 0402 1740,5110 r0 top value=4.87k
R70 "CRCW040251R0JNED" 0402 1920,5240 r270 bottom value=51
R71 "CRCW06030000Z0EA" 0603 1854,2011.59 r270 bottom value=0
R72 "CRCW06030000Z0EA" 0603 2145,2085 r90 bottom value=0
R100 "CRCW04021M00FKED" 0402 660,5920 r90 top value=1.00Meg
R101 "CRCW040251K0FKED" 0402 120,5430 r0 top
R102 "CRCW040230K0FKED" 0402 120,5528 r180 top value=30.0k
R103 "CRCW040224R3FKED" 0402 520,5490 r0 top value=24.3
R104 "CRCW040224R3FKED" 0402 520,5430 r0 top value=24.3
R105 "CRCW0402680RJNED" 0402 280,5510 r270 top value=680
S1 "1188E-1K2-V-TR" SW_1188E 2180,4400 r180 top
S2 "218-2LPST" SW_218-2LP 1230,1710 r270 top
S3 "CAS-D20TA" SW_CAS-D20TA 940,930 r180 top
S4 "CAS-220TA" SW_CAS-220TA 1000,1710 r0 top
S6 "CAS-220TA" SW_CAS-220TA 1135,3885 r0 top
S8 "CAS-220TA" SW_CAS-220TA 1130,4205 r180 top
S9 "CAS-220TA" SW_CAS-220TA 1720,1290 r0 top
TP1 "TESTPOINT" TESTPOINT 1560,2920 r0 top
TP2 "TESTPOINT" TESTPOINT 920,2260 r0 top
TP3 "TESTPOINT" TESTPOINT 650,2850 r0 top
TP4 "TESTPOINT" TESTPOINT 1500,1940 r0 top
TP5 "TESTPOINT" TESTPOINT 1060,620 r0 top
TP6 "TESTPOINT" TESTPOINT 2070,1820 r0 top
U1 "F280049CPZS" PZ0100A_N 1150,2690 r315 top
U2 "MSP432E401YTPDT" PDT0128A 1600,5480 r0 top locked
U3 "ADuM3160BRWZ" SOIC-16 840,5560 r0 top
U4 "TPS3702CX33DDCR" DDC0006A_N 2140,4770 r90 top
U5 "LMR62421XMFX/NOPB" DBV0005A_N 590,4830 r90 top
U6 "SN74LVC2G07DBVR" DBV0006A_N 1580,4270 r90 top
U7 "TXB0106PWR" PW0016A_N 1240,910 r270 top
U8 "SN74LV4053ATPWRQ1" PW0016A_L 1390,1310 r180 top
U9 "SN74LV4053ATPWRQ1" PW0016A_L 1010,1310 r180 top
U10 "SN65HVD234DR" D0008A_L 1590,825 r270 top
U12 "TPD6E004RSER" RSE0008A 1430,4980 r180 top
U100 "TPD4E004DRYR" DRY0006A 435,5845 r180 top
U101 "TPS79601DRBR" DRB0008B 170,5650 r270 top
USB101 "1051640001" Molex_1051640001 445,6110 r180 top
Y1 "NX3225GA-16.000M-STD-CRG-1" NDK_NX3225GA 2040,5610 r180 top
Y2 "ECS-200-18-30B-AGN-TR" ECS_ECX-53B 1581.21,2362.93 r90 top
ZZ2 "These assemblies are ESD sensitive, ESD precautions shall be observed." AssemblyNote 95,7342 r0 top
ZZ3 "These assemblies must be clean and free from flux and all contaminants. Use of no clean flux is not acceptable." AssemblyNote 95,7192 r0 top
ZZ4 "These assemblies must comply with workmanship standards IPC-A-610 Class 2, unless otherwise specified." AssemblyNote 95,7042 r0 top

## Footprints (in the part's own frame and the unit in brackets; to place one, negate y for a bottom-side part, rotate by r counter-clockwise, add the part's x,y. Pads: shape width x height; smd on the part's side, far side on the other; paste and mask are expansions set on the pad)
0402 [mm] "0402 from SM-752 data"
  rect 0.8x0.6 smd: 1(-0.6,0) 2(0.6,0)
  silkscreen extent -1.22,-0.52 1.22,0.52, body extent -0.55,-0.3 0.55,0.3, height 0.6
0603 [mm] "0603 from SM-752 data"
  rect 1x0.95 smd: 1(-0.8,0) 2(0.8,0)
  silkscreen extent -1.52,-0.69 1.52,0.69, body extent -0.87,-0.47 0.87,0.47, height 1
0805 [mm] "0805 from SM-752 data"
  rect 1.3x1.5 smd: 1(-0.85,0) 2(0.85,0)
  silkscreen extent -1.72,-0.97 1.72,0.97, body extent -1.1,-0.72 1.1,0.72, height 1.45
1210_220 [mm] "1210"
  rect 1.3x2.7 smd: 1(-1.45,0) 2(1.45,0)
  silkscreen extent -2.32,-1.57 2.32,1.57, body extent -1.7,-1.35 1.7,1.35, height 2.2
1812 [mm]
  rect 1.6x3.4 smd: 1(-2,0) 2(2,0)
  silkscreen extent -0.8,-1.6 0.8,1.6, body extent -2.4,-1.7 2.4,1.7, height 1.35
AssemblyNote [mil] "Assembly Note"
BoosterPack_40pin_J1J3 [mm] "Receptacle, 2.54mm, 10x2, TH"
  rrect6% 1.55x1.55 hole 1.02: 1(1.27,11.43)
  round 1.55 hole 1.02: 2(1.27,8.89) 3(1.27,6.35) 4(1.27,3.81) 5(1.27,1.27) 6(1.27,-1.27) 7(1.27,-3.81) 8(1.27,-6.35) 9(1.27,-8.89) 10(1.27,-11.43) 21(-1.27,11.43) 22(-1.27,8.89) 23(-1.27,6.35) 24(-1.27,3.81) 25(-1.27,1.27) 26(-1.27,-1.27) 27(-1.27,-3.81) 28(-1.27,-6.35) 29(-1.27,-8.89) 30(-1.27,-11.43)
  silkscreen extent -7.62,-12.95 7.62,12.95, body extent -2.48,-12.95 2.48,12.95, height 8.51
BoosterPack_40pin_J2J4 [mm] "Receptacle, 2.54mm, 10x2, TH"
  round 1.55 hole 1.02: 11(-1.27,-11.43) 12(-1.27,-8.89) 13(-1.27,-6.35) 14(-1.27,-3.81) 15(-1.27,-1.27) 16(-1.27,1.27) 17(-1.27,3.81) 18(-1.27,6.35) 19(-1.27,8.89) 20(-1.27,11.43) 31(1.27,-11.43) 32(1.27,-8.89) 33(1.27,-6.35) 34(1.27,-3.81) 35(1.27,-1.27) 36(1.27,1.27) 37(1.27,3.81) 38(1.27,6.35) 39(1.27,8.89) 40(1.27,11.43)
  silkscreen extent -7.62,-12.95 2.48,12.95, body extent -2.48,-12.95 2.48,12.95, height 8.51
CE_Mark_5mm [mil] "Minimum text height for CE Mark"
  silkscreen extent -138,-98 138,98
D0008A_L [mm] "SOIC, 8-Leads, Body 4.9x3.9mm, Pitch 1.27mm, IPC High Density"
  oval 1.25x0.55 smd: 1(-2.625,1.905) 2(-2.625,0.635) 3(-2.625,-0.635) 4(-2.625,-1.905) 5(2.625,-1.905) 6(2.625,-0.635) 7(2.625,0.635) 8(2.625,1.905)
  silkscreen extent -3.1,-2.5 0.9,2.5, body extent -3,-2.45 3,2.45, height 1.63
DBV0005A_N [mm] "SOT23, 5-Leads, Body 2.9x1.6mm, Pitch 0.95mm, Lead Span 2.8mm, IPC Medium Density"
  rrect17% 1x0.6 smd: 1(-1.375,0.95) 2(-1.375,0) 3(-1.375,-0.95) 4(1.375,-0.95) 5(1.375,0.95)
  silkscreen extent -0.25,-1.55 0.25,1.55, body extent -1.42,-1.46 1.42,1.46, height 1.09
DBV0006A_N [mm] "SOT23, 6-Leads, Body 2.9x1.6mm, Pitch 0.95mm, Lead Span 2.8mm, IPC Medium Density"
  rrect17% 1x0.6 smd: 1(-1.375,0.95) 2(-1.375,0) 3(-1.375,-0.95) 4(1.375,-0.95) 5(1.375,0) 6(1.375,0.95)
  silkscreen extent -1.67,-1.55 0.5,1.55, body extent -1.42,-1.46 1.42,1.46, height 1.12
DDC0006A_N [mm]
  rrect17% 1x0.6 smd: 1(-1.375,0.95) 2(-1.375,0) 3(-1.375,-0.95) 4(1.375,-0.95) 5(1.375,0) 6(1.375,0.95)
  silkscreen extent -1.75,-1.52 0.7,1.53, body extent -1.43,-1.48 1.43,1.49, height 0.92
DRB0008B [mm] "SON, 8-Leads, Body 3x3mm, Pitch 0.65mm, Thermal Pad 2.4x1.65mm, TI Recommended"
  rrect33% 0.6x0.3 smd: 1(-1.4,0.975) 2(-1.4,0.325) 3(-1.4,-0.325) 4(-1.4,-0.975) 5(1.4,-0.975) 6(1.4,-0.325) 7(1.4,0.325) 8(1.4,0.975)
  rrect9% 1.47x1.06 on Top Paste: 9(0,0.63) 9(0,-0.63)
  rrect6% 1.65x2.4 smd paste-1.2: 9(0,0)
  silkscreen extent -1.73,-1.73 1.73,1.73, body extent -1.5,-1.5 1.5,1.5, height 0.96
DRY0006A [mm] "PSON, 6-Leads, Body 1x1.45mm, Pitch 0.5mm, TI Recommended"
  rrect50% 0.35x0.2 smd: 1(-0.275,0.5)
  rrect50% 0.3x0.2 smd: 2(-0.3,0) 3(-0.3,-0.5) 4(0.3,-0.5) 5(0.3,0) 6(0.3,0.5)
  body extent -0.5,-0.72 0.5,0.73, height 0.58
ECS_ECX-53B [mm] "SMD, 4-Leads, Body 5x3.2mm"
  rect 1.25x1.6 smd: 1(-1.1,1.85) 2(-1.1,-1.85) 3(1.1,-1.85) 4(1.1,1.85)
  silkscreen extent -2.05,-2.7 1.83,2.73, body extent -1.7,-2.6 1.7,2.6, height 0.86
FCC_disclaimer [mil]
Fiducial10-20 [mm]
  round 1 smd mask+0.5: 1(0,0)
  Top Signal keep-out circle w1.178: c0,0 r0.5
INSTASPIN_FOC_LOGO [mil] "INSTASPIN FOC LOGO"
  silkscreen extent -122,-122 119,118
LED_LTST-C171 [mm] "LITE-ON"
  rect 1.2x1.2 smd: 1(-1.05,0) 2(1.05,0)
  silkscreen extent -1.6,-1 2.2,1, body extent -1.05,-0.67 1.05,0.67, height 0.8
LTST-C170TBKT_Blue [mm] "LITE-ON"
  rect 1.2x1.2 smd: 1(-1.05,0) 2(1.05,0)
  silkscreen extent -1.6,-1 2.2,1, body extent -1.05,-0.67 1.05,0.67, height 1.2
Molex_1051640001 [mm] "Receptacle, USB 2.0, Micro B, 5 Pos, 0.65mm Pitch, R/A, SMT"
  rrect22% 0.45x1.38 smd: 1(1.3,4.11) 2(0.65,4.11) 3(0,4.11) 4(-0.65,4.11) 5(-1.3,4.11)
  rrect7% 1.475x2.1 smd: 6(-2.462,3.75) 11(2.462,3.75)
  rrect100% 1.4x2.1 hole 0.6 slot 1.3 at 90 deg: 7(-3.95,1.45) 10(3.95,1.45)
  rrect7% 1.375x1.9 smd: 8(-0.937,1.45) 9(0.937,1.45)
  silkscreen extent 1.2,5.1 1.4,5.4, body extent -4.1,-0.7 4.1,4.47, height 2.45
NDK_NX3225GA [mm] "NDK"
  rect 1.2x1.4 smd: 1(-0.8,1.1) 2(-0.8,-1.1) 3(0.8,-1.1) 4(0.8,1.1)
  silkscreen extent -1.9,-0.1 1.4,2, body extent -1.3,-1.65 1.3,1.65, height 0.9
NPTH125mil [mil]
  round 120 hole 125 unplated mask+15: 1(0,0)
PDT0128A [mm] "Thin QFP, 128-Leads, Body 14x14mm, Pitch 0.4mm"
  oval 1.4x0.2 smd: 1(-7.7,6.2) 2(-7.7,5.8) 3(-7.7,5.4) 4(-7.7,5) 5(-7.7,4.6) 6(-7.7,4.2) 7(-7.7,3.8) 8(-7.7,3.4) 9(-7.7,3) 10(-7.7,2.6) 11(-7.7,2.2) 12(-7.7,1.8) 13(-7.7,1.4) 14(-7.7,1) 15(-7.7,0.6) 16(-7.7,0.2) 17(-7.7,-0.2) 18(-7.7,-0.6) 19(-7.7,-1) 20(-7.7,-1.4) 21(-7.7,-1.8) 22(-7.7,-2.2) 23(-7.7,-2.6) 24(-7.7,-3) 25(-7.7,-3.4) 26(-7.7,-3.8) 27(-7.7,-4.2) 28(-7.7,-4.6) 29(-7.7,-5) 30(-7.7,-5.4) 31(-7.7,-5.8) 32(-7.7,-6.2) 65(7.7,-6.2) 66(7.7,-5.8) 67(7.7,-5.4) 68(7.7,-5) 69(7.7,-4.6) 70(7.7,-4.2) 71(7.7,-3.8) 72(7.7,-3.4) 73(7.7,-3) 74(7.7,-2.6) 75(7.7,-2.2) 76(7.7,-1.8) 77(7.7,-1.4) 78(7.7,-1) 79(7.7,-0.6) 80(7.7,-0.2) 81(7.7,0.2) 82(7.7,0.6) 83(7.7,1) 84(7.7,1.4) 85(7.7,1.8) 86(7.7,2.2) 87(7.7,2.6) 88(7.7,3) 89(7.7,3.4) 90(7.7,3.8) 91(7.7,4.2) 92(7.7,4.6) 93(7.7,5) 94(7.7,5.4) 95(7.7,5.8) 96(7.7,6.2)
  oval 0.2x1.4 smd: 33(-6.2,-7.7) 34(-5.8,-7.7) 35(-5.4,-7.7) 36(-5,-7.7) 37(-4.6,-7.7) 38(-4.2,-7.7) 39(-3.8,-7.7) 40(-3.4,-7.7) 41(-3,-7.7) 42(-2.6,-7.7) 43(-2.2,-7.7) 44(-1.8,-7.7) 45(-1.4,-7.7) 46(-1,-7.7) 47(-0.6,-7.7) 48(-0.2,-7.7) 49(0.2,-7.7) 50(0.6,-7.7) 51(1,-7.7) 52(1.4,-7.7) 53(1.8,-7.7) 54(2.2,-7.7) 55(2.6,-7.7) 56(3,-7.7) 57(3.4,-7.7) 58(3.8,-7.7) 59(4.2,-7.7) 60(4.6,-7.7) 61(5,-7.7) 62(5.4,-7.7) 63(5.8,-7.7) 64(6.2,-7.7) 97(6.2,7.7) 98(5.8,7.7) 99(5.4,7.7) 100(5,7.7) 101(4.6,7.7) 102(4.2,7.7) 103(3.8,7.7) 104(3.4,7.7) 105(3,7.7) 106(2.6,7.7) 107(2.2,7.7) 108(1.8,7.7) 109(1.4,7.7) 110(1,7.7) 111(0.6,7.7) 112(0.2,7.7) 113(-0.2,7.7) 114(-0.6,7.7) 115(-1,7.7) 116(-1.4,7.7) 117(-1.8,7.7) 118(-2.2,7.7) 119(-2.6,7.7) 120(-3,7.7) 121(-3.4,7.7) 122(-3.8,7.7) 123(-4.2,7.7) 124(-4.6,7.7) 125(-5,7.7) 126(-5.4,7.7) 127(-5.8,7.7) 128(-6.2,7.7)
  silkscreen extent -7.7,-6.3 6.3,6.99, body extent -8,-8 8,8, height 1.07
PW0016A_L [mm] "TSOP, 16-Leads, Body 5x4.4mm, Pitch 0.65mm, IPC High Density"
  oval 1.2x0.4 smd: 1(-2.85,2.275) 2(-2.85,1.625) 3(-2.85,0.975) 4(-2.85,0.325) 5(-2.85,-0.325) 6(-2.85,-0.975) 7(-2.85,-1.625) 8(-2.85,-2.275) 9(2.85,-2.275) 10(2.85,-1.625) 11(2.85,-0.975) 12(2.85,-0.325) 13(2.85,0.325) 14(2.85,0.975) 15(2.85,1.625) 16(2.85,2.275)
  silkscreen extent -2,-2.55 1.85,2.55, body extent -3.21,-2.5 3.21,2.5, height 1
PW0016A_N [mm] "TSOP, 16-Leads, Body 5x4.4mm, Pitch 0.65mm, IPC Medium Density"
  oval 1.4x0.45 smd: 1(-2.95,2.275) 2(-2.95,1.625) 3(-2.95,0.975) 4(-2.95,0.325) 5(-2.95,-0.325) 6(-2.95,-0.975) 7(-2.95,-1.625) 8(-2.95,-2.275) 9(2.95,-2.275) 10(2.95,-1.625) 11(2.95,-0.975) 12(2.95,-0.325) 13(2.95,0.325) 14(2.95,0.975) 15(2.95,1.625) 16(2.95,2.275)
  silkscreen extent -3.5,-2.55 1.85,2.75, body extent -3.21,-2.5 3.21,2.5, height 1
PZ0100A_N [mm] "TSQFP, 100-Leads, Body 16.2x16.2mm (max), Pitch 0.50mm, IPC Medium Density"
  oval 1.45x0.3 smd: 1(-7.725,6) 2(-7.725,5.5) 3(-7.725,5) 4(-7.725,4.5) 5(-7.725,4) 6(-7.725,3.5) 7(-7.725,3) 8(-7.725,2.5) 9(-7.725,2) 10(-7.725,1.5) 11(-7.725,1) 12(-7.725,0.5) 13(-7.725,0) 14(-7.725,-0.5) 15(-7.725,-1) 16(-7.725,-1.5) 17(-7.725,-2) 18(-7.725,-2.5) 19(-7.725,-3) 20(-7.725,-3.5) 21(-7.725,-4) 22(-7.725,-4.5) 23(-7.725,-5) 24(-7.725,-5.5) 25(-7.725,-6) 51(7.725,-6) 52(7.725,-5.5) 53(7.725,-5) 54(7.725,-4.5) 55(7.725,-4) 56(7.725,-3.5) 57(7.725,-3) 58(7.725,-2.5) 59(7.725,-2) 60(7.725,-1.5) 61(7.725,-1) 62(7.725,-0.5) 63(7.725,0) 64(7.725,0.5) 65(7.725,1) 66(7.725,1.5) 67(7.725,2) 68(7.725,2.5) 69(7.725,3) 70(7.725,3.5) 71(7.725,4) 72(7.725,4.5) 73(7.725,5) 74(7.725,5.5) 75(7.725,6)
  oval 0.3x1.45 smd: 26(-6,-7.725) 27(-5.5,-7.725) 28(-5,-7.725) 29(-4.5,-7.725) 30(-4,-7.725) 31(-3.5,-7.725) 32(-3,-7.725) 33(-2.5,-7.725) 34(-2,-7.725) 35(-1.5,-7.725) 36(-1,-7.725) 37(-0.5,-7.725) 38(0,-7.725) 39(0.5,-7.725) 40(1,-7.725) 41(1.5,-7.725) 42(2,-7.725) 43(2.5,-7.725) 44(3,-7.725) 45(3.5,-7.725) 46(4,-7.725) 47(4.5,-7.725) 48(5,-7.725) 49(5.5,-7.725) 50(6,-7.725) 76(6,7.725) 77(5.5,7.725) 78(5,7.725) 79(4.5,7.725) 80(4,7.725) 81(3.5,7.725) 82(3,7.725) 83(2.5,7.725) 84(2,7.725) 85(1.5,7.725) 86(1,7.725) 87(0.5,7.725) 88(0,7.725) 89(-0.5,7.725) 90(-1,7.725) 91(-1.5,7.725) 92(-2,7.725) 93(-2.5,7.725) 94(-3,7.725) 95(-3.5,7.725) 96(-4,7.725) 97(-4.5,7.725) 98(-5,7.725) 99(-5.5,7.725) 100(-6,7.725)
  silkscreen extent -7.7,-6.3 6.3,6.82, body extent -8.01,-8.01 8.01,8.01, height 1.5
RSE0008A [mm] "QFN, 8-Leads, Body 1.5x1.5mm, Pitch 0.5mm, TI Recommended"
  rrect40% 0.55x0.25 smd: 1(-0.675,0.5) 3(-0.675,-0.5) 5(0.675,-0.5) 7(0.675,0.5)
  rrect50% 0.55x0.2 smd: 2(-0.675,0) 6(0.675,0)
  rrect33% 0.3x0.6 smd: 4(0,-0.65) 8(0,0.65)
  silkscreen extent -1.02,-0.93 0.78,0.93, body extent -0.75,-0.75 0.75,0.75, height 0.6
Samtec_FTSH-105-01-x-DV-K [mm] "Header(Shrouded), 1.27mm, 5x2, SMT"
  rect 2.79x0.74 smd: 1(-2.035,2.54) 2(2.035,2.54) 3(-2.035,1.27) 4(2.035,1.27) 5(-2.035,0) 6(2.035,0) 7(-2.035,-1.27) 8(2.035,-1.27) 9(-2.035,-2.54) 10(2.035,-2.54)
  silkscreen extent -3.73,-3.48 3.73,3.48, body extent -2.92,-3.18 2.92,3.17, height 6.13
SOD-123 [mm] "On Semi recommended land pattern"
  rect 0.915x1.22 smd: 1(-1.637,0) 2(1.637,0)
  silkscreen extent -2.74,-1.17 2.03,1.17, body extent -1.93,-0.9 1.93,0.9, height 1.35
SOIC-16 [mm] "SOIC, 16-Leads, Body 10.3x7.5mm, Pitch 1.27mm"
  rrect15% 2.25x0.65 smd: 1(-4.75,4.445) 2(-4.75,3.175) 3(-4.75,1.905) 4(-4.75,0.635) 5(-4.75,-0.635) 6(-4.75,-1.905) 7(-4.75,-3.175) 8(-4.75,-4.445) 9(4.75,-4.445) 10(4.75,-3.175) 11(4.75,-1.905) 12(4.75,-0.635) 13(4.75,0.635) 14(4.75,1.905) 15(4.75,3.175) 16(4.75,4.445)
  silkscreen extent -4.87,-5.25 3.8,5.44, body extent -5.32,-5.24 5.32,5.25, height 2.64
SW_218-2LP [mm] "SMD, 4-Leads, Body 3.71x5.8mm, Pitch 1.27mm"
  rect 1.27x0.76 smd: 1(-3.81,0.635) 2(-3.81,-0.635) 3(3.81,-0.635) 4(3.81,0.635)
  silkscreen extent -2.9,-1.86 2.9,2.09, body extent -4.22,-1.86 4.22,1.85, height 2.62
SW_1188E [mm] "SMD, 4-Leads, Body 7.8x3.5mm"
  rrect10% 1x1.45 smd: 1(-1.1,3.375) 2(-1.1,-3.375)
  rrect11% 1.3x0.9 smd: 3(0.7,2.1) 4(0.7,-2.1)
  round 0 hole 0.9 unplated: ""(-0.35,1.15) ""(-0.35,-1.15)
  silkscreen extent -1.98,-2.28 0.95,2.28, body extent -2.55,-3.9 1.05,3.9, height 3.5
SW_CAS-220TA [mm] "COPAL ELECTRONICS"
  rect 1.6x1 smd: 1(-1.85,1.75) 2(-1.85,0) 3(-1.85,-1.75) 4(1.85,1.75) 5(1.85,0) 6(1.85,-1.75)
  silkscreen extent -2.1,-2.9 2,3.7, body extent -2.1,-2.85 2.1,2.85, height 2.51
SW_CAS-D20TA [mm] "SMD, 6-Leads, Body 5.4x3.9mm, Pitch 1.75mm"
  rect 1.6x1 smd: 1(-1.85,1.75) 2(-1.85,0) 3(-1.85,-1.75) 4(1.85,1.75) 5(1.85,0) 6(1.85,-1.75)
  silkscreen extent -1.95,-2.7 1.95,2.9, body extent -2.1,-2.7 2.1,2.7, height 2.5
Tag_TC2050-NL [mil] "Footprint for Tag-Connect TC2050 No-Legs cables"
  round 31 smd paste-15.75: 1(-25,100) 2(-25,50) 3(-25,0) 4(-25,-50) 5(-25,-100) 6(25,-100) 7(25,-50) 8(25,0) 9(25,50) 10(25,100)
  round 39 hole 39 unplated: MH1(0,150) MH2(-40,-150) MH3(40,-150)
  silkscreen extent -105,-200 75,200
TESTPOINT [mil]
  round 80 hole 37.99: 1(0,0)
TI_Stacked_Overlay_Small [mil]
  silkscreen extent -418,-98 418,98
TSW-102-07-G-D [mm] "Samtec 100mil, 2x2, 230 mil above insulator"
  rrect6% 1.65x1.65 hole 1.016: 1(-1.27,-1.27)
  round 1.65 hole 1.016: 2(-1.27,1.27) 3(1.27,-1.27) 4(1.27,1.27)
  silkscreen extent -3.56,-2.54 2.54,2.54, body extent -2.54,-2.54 2.54,2.54, height 8.38
TSW-104-07-G-D [mm] "Samtec 100mil, 2x4, 230 mil above insulator"
  rrect6% 1.65x1.65 hole 1.016: 1(-3.81,-1.27)
  round 1.65 hole 1.016: 2(-3.81,1.27) 3(-1.27,-1.27) 4(-1.27,1.27) 5(1.27,-1.27) 6(1.27,1.27) 7(3.81,-1.27) 8(3.81,1.27)
  silkscreen extent -6.11,-2.54 5.08,2.54, body extent -5.08,-2.54 5.08,2.54, height 8.38
TSW-105-07-G-D [mm] "Samtec 100mil, 2x5, 230 mil above insulator"
  rrect6% 1.65x1.65 hole 1.016: 1(-5.08,-1.27)
  round 1.65 hole 1.016: 2(-5.08,1.27) 3(-2.54,-1.27) 4(-2.54,1.27) 5(0,-1.27) 6(0,1.27) 7(2.54,-1.27) 8(2.54,1.27) 9(5.08,-1.27) 10(5.08,1.27)
  silkscreen extent -7.37,-2.54 6.35,2.54, body extent -6.35,-2.54 6.35,2.54, height 8.38
TSW-105-07-X-S [mm] "Samtec 100mil, 1x5, 230 mil above insulator"
  rrect6% 1.65x1.65 hole 1.016: 1(-5.08,-0.025)
  round 1.65 hole 1.016: 2(-2.54,0) 3(0,0) 4(2.54,0) 5(5.08,0)
  silkscreen extent -7.05,-1.25 6.37,1.25, body extent -6.35,-1.27 6.35,1.27, height 8.38
WE-TPC_2828 [mm] "WURTH"
  rect 1x3.2 smd: 1(-1.1,0) 2(1.1,0)
  body extent -1.5,-1.5 1.5,1.5, height 3
WEEE_Minimum [mil] "WEEElie bin"
  silkscreen extent -95,-172 99,104
WL-SMCW_RED_0805 [mm] "SMD, 2-Leads, Body 1.6x0.8mm"
  rect 1.1x1.2 smd: 1(-1.05,0) 2(1.05,0)
  silkscreen extent -2.4,-1.1 1.5,1.1, body extent -1,-0.62 1,0.63, height 0.7
Wurth_60900213421 [mil] "Shunt, 2.54mm, Black"
  round 1 on Mech3: 0(0,0)
  body extent -98,-48 98,48, height 338
WURTH_61300211121 [mm] "Header, 2.54mm, 2x1, TH"
  rect 1.65x1.65 hole 1.15: 1(-1.27,0)
  round 1.65 hole 1.15: 2(1.27,0)
  silkscreen extent -2.54,-1.27 2.54,1.6, body extent -2.54,-1.27 2.54,1.27, height 8.54
WURTH_61300311121 [mm] "Header, 2.54mm, 3x1, TH"
  rect 1.65x1.65 hole 1.15: 1(-2.54,0)
  round 1.65 hole 1.15: 2(0,0) 3(2.54,0)
  silkscreen extent -3.81,-1.27 3.81,1.6, body extent -3.81,-1.27 3.81,1.27, height 8.54

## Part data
C1 C2 C6 C11 C12 C13 C14 C21 C22 C23 C24 C25 C37 C40 C41 C42 C49 C105 C106: library part CMP-0006629-2, "CAP, CERM, 0.1 uF, 10 V, +/- 10%, X7R, 0402", Cap_Case=0402, Manufacturer=MuRata, Supplier Part Number 1=GRM155R71A104KA01D-ND, TempCo=X7R, Tolerance_%=10%, Value1=Unknown, Value2=10V, ValueDisplayed=0.1uF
